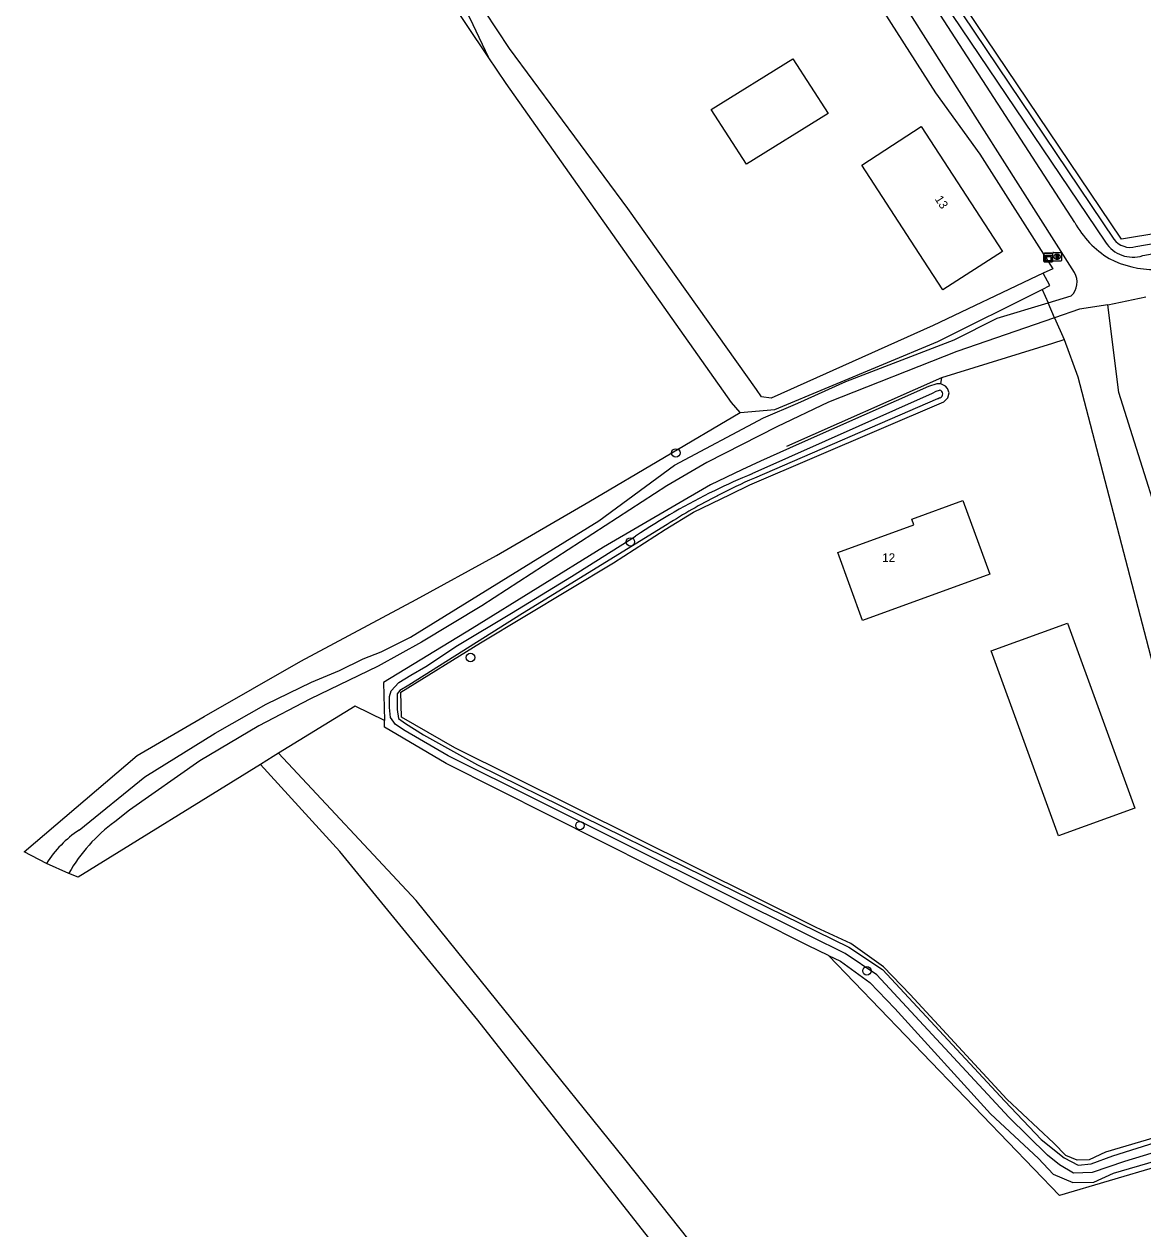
# Model space of a CAD drawing. Extents: x 163863 to 164644, y 379566 to 382155.
# Drawn here: x 164255.7 to 164384.5, y 381487.2 to 381625.9 of the extents above; entities that cross this region are included whole.
import ezdxf

# ---------------------------------------------------------------- set-up
doc = ezdxf.new("R2010")
doc.units = 0
for name, color, linetype in [('IMGEO_Boom', 7, 'Continuous'), ('IMGEO_Bouwland', 7, 'Continuous'), ('IMGEO_Erf', 7, 'Continuous'), ('IMGEO_Grasland_overig', 7, 'Continuous'), ('IMGEO_Groenvoorziening', 7, 'Continuous'), ('IMGEO_Haag', 7, 'Continuous'), ('IMGEO_Hek', 7, 'Continuous'), ('IMGEO_Kast', 7, 'Continuous'), ('IMGEO_Pand', 7, 'Continuous'), ('IMGEO_Pand_nummerreeks', 7, 'Continuous'), ('IMGEO_Rijbaan_lokaal_onverhard', 7, 'Continuous'), ('IMGEO_Rioolput', 7, 'Continuous'), ('IMGEO_Waterloop', 7, 'Continuous')]:
    doc.layers.add(name, color=color, linetype=linetype)

msp = doc.modelspace()

# ---------------------------------------------------------------- linework, layer by layer
at = {"layer": 'IMGEO_Boom'}
for centre in [(164330.75, 381576.5), (164325.53, 381566.25), (164307.12, 381552.94), (164319.72, 381533.59), (164352.76, 381516.86)]:
    msp.add_circle(centre, 0.489, dxfattribs=at)
at = {"layer": 'IMGEO_Bouwland'}
msp.add_lwpolyline([(164348.35, 381518.62), (164345.94, 381519.8), (164304.33, 381540.74), (164297.21, 381544.93), (164297.2, 381545.69)], dxfattribs=at)
at = {"layer": 'IMGEO_Erf'}
msp.add_lwpolyline([(164399.71, 381501.75), (164380.24, 381495.98), (164378.34, 381495.1), (164376.95, 381495.07), (164375.66, 381495.6), (164374.28, 381497.03), (164368.85, 381502.09), (164357.74, 381514.15), (164354.66, 381517.34), (164350.89, 381520.01), (164346.92, 381521.84), (164305.32, 381542.54), (164299.19, 381546.09), (164299.1, 381548.97), (164308.27, 381554.65), (164323.57, 381563.86), (164329.55, 381567.7), (164332.8, 381569.66), (164337.03, 381571.73), (164339.27, 381572.83), (164361.61, 381582.39), (164362.09, 381582.86), (164362.24, 381583.41), (164362.04, 381583.93), (164361.82, 381584.19), (164361.25, 381584.45)], dxfattribs=at)
at = {"layer": 'IMGEO_Grasland_overig'}
for points in [[(164309.17, 381622.09), (164287.09, 381655.07)], [(164372.93, 381595.33), (164373.62, 381593.79)], [(164262.05, 381533.06), (164269.61, 381539.21), (164277.71, 381544.24), (164283.59, 381547.57), (164288.81, 381550.12), (164292.05, 381551.44), (164294.75, 381552.79), (164296.85, 381553.59), (164300.23, 381555.29), (164321.9, 381568.69), (164330.62, 381575.1), (164340.85, 381580.53), (164344.81, 381582.22), (164350.33, 381584.74), (164362.79, 381589.53), (164367.77, 381592.02), (164373.62, 381593.79)], [(164392.11, 381552.47), (164390.65, 381553.68), (164390.08, 381554.71), (164388.77, 381561.19), (164381.76, 381583.47), (164380.51, 381593.56)], [(164374.37, 381592.06), (164363.11, 381588.17), (164348.34, 381582.35), (164342.38, 381579.5), (164334.32, 381575.4), (164329.74, 381572.7), (164308.43, 381558.91), (164301.49, 381554.72), (164296.49, 381551.95), (164288.63, 381548.14), (164282.77, 381545.07), (164275.97, 381541.06), (164267.86, 381535.37), (164266.17, 381534.03)], [(164374.37, 381592.06), (164375.48, 381589.55)], [(164361.25, 381584.45), (164361.39, 381585.17), (164374.16, 381589.15), (164375.48, 381589.55)], [(164375.48, 381589.55), (164377.05, 381585.25), (164394.23, 381519.23)], [(164361.25, 381584.45), (164360.81, 381584.45), (164359.85, 381584.14), (164344.96, 381577.54), (164340.51, 381575.55), (164338.35, 381574.54), (164334.75, 381572.82), (164322.44, 381565.66), (164307.31, 381556.3), (164297.1, 381550.07), (164297.2, 381545.69)], [(164258.3, 381529.24), (164255.73, 381530.58), (164268.74, 381541.65), (164276.47, 381546.15), (164287.59, 381552.54), (164300.85, 381559.61), (164310.1, 381564.69), (164320.74, 381570.88), (164338.17, 381581.17)], [(164297.2, 381545.69), (164293.83, 381547.35), (164285.02, 381541.92)], [(164285.02, 381541.92), (164284.42, 381541.54), (164282.94, 381540.64)], [(164409.07, 381444.14), (164409.6, 381438.92), (164393.19, 381411.03), (164380.14, 381426.39), (164361.95, 381448.81), (164345.91, 381468.69), (164324.9, 381495.18), (164300.88, 381524.96), (164285.02, 381541.92)], [(164282.94, 381540.64), (164261.94, 381527.66), (164260.87, 381528.09)], [(164392.18, 381406.36), (164355.54, 381450.6), (164307.96, 381511.18), (164292.08, 381530.61), (164282.94, 381540.64)], [(164260.87, 381528.09), (164258.3, 381529.24)], [(164348.35, 381518.62), (164349.7, 381517.97), (164353.09, 381515.54), (164355.98, 381512.51), (164367, 381500.41), (164372.5, 381495.24), (164374.19, 381493.46), (164376.45, 381492.51), (164378.9, 381492.55), (164381.15, 381493.56), (164399.72, 381498.97), (164402.22, 381489.44), (164402.44, 381487.77), (164403.46, 381487.71)], [(164404.26, 381474.32), (164397.81, 381497.74), (164374.92, 381491), (164348.35, 381518.62)]]:
    msp.add_lwpolyline(points, dxfattribs=at)
for centre, radius, start, end in [((164277.4, 381518.7), 19.01, 126.2236, 150.3885), ((164269.14, 381522.37), 12.83, 123.5518, 147.6149)]:
    msp.add_arc(centre, radius, start, end, dxfattribs=at)
at = {"layer": 'IMGEO_Groenvoorziening'}
msp.add_lwpolyline([(164342.85, 381642.58), (164344.82, 381642.8), (164360.65, 381617.95), (164365.76, 381610.9), (164374.16, 381597.69), (164373.03, 381597.19)], dxfattribs=at)
at = {"layer": 'IMGEO_Haag'}
msp.add_lwpolyline([(164407.8, 381604.43), (164407.63, 381605.35), (164382.05, 381601.1), (164338.92, 381665.18), (164338.35, 381664.78)], dxfattribs=at)
at = {"layer": 'IMGEO_Hek'}
for points in [[(164374.16, 381589.15), (164375.48, 381589.55)], [(164343.52, 381577.27), (164361.39, 381585.17)]]:
    msp.add_lwpolyline(points, dxfattribs=at)
at = {"layer": 'IMGEO_Kast'}
for p, q in [((164373.12, 381598.57), (164373.12, 381599.41)), ((164373.12, 381599.41), (164373.12, 381598.57)), ((164373.2, 381599.49), (164374.04, 381599.49)), ((164374.04, 381599.49), (164373.2, 381599.49)), ((164374.12, 381599.42), (164374.12, 381598.58)), ((164374.12, 381598.58), (164374.12, 381599.42)), ((164374.05, 381598.49), (164373.21, 381598.49)), ((164373.21, 381598.49), (164374.05, 381598.49))]:
    msp.add_line(p, q, dxfattribs=at)
for points in [[(164373.32, 381599.28), (164373.92, 381599.28), (164373.92, 381599.2), (164373.32, 381599.2), (164373.32, 381599.28)], [(164373.32, 381599.11), (164373.92, 381599.11), (164373.92, 381598.62), (164373.32, 381598.62), (164373.32, 381599.11)]]:
    msp.add_lwpolyline(points, dxfattribs=at)
msp.add_circle((164373.4, 381598.96), 0.0377, dxfattribs=at)
for centre, start, end in [((164373.2, 381599.41), 92.4484, 184.2845), ((164373.2, 381599.41), 92.4484, 184.2845), ((164374.04, 381599.41), 2.4484, 94.2845), ((164374.04, 381599.41), 2.4484, 94.2845), ((164373.2, 381598.57), 182.4484, 274.2845), ((164373.2, 381598.57), 182.4484, 274.2845), ((164374.04, 381598.57), 272.4484, 4.2845), ((164374.04, 381598.57), 272.4484, 4.2845)]:
    msp.add_arc(centre, 0.0779, start, end, dxfattribs=at)
at = {"layer": 'IMGEO_Pand'}
for points in [[(164338.91, 381609.75), (164334.83, 381616.04), (164344.23, 381621.88), (164348.31, 381615.59), (164338.91, 381609.75)], [(164358.78, 381599.46), (164352.17, 381609.65), (164354.82, 381611.38), (164359.01, 381614.1), (164368.35, 381599.71), (164361.5, 381595.27), (164358.78, 381599.46)], [(164352.26, 381557.21), (164349.42, 381565.03), (164358.15, 381568.22), (164357.92, 381568.87), (164363.81, 381571.02), (164366.9, 381562.54), (164352.26, 381557.21)], [(164367.06, 381553.7), (164375.84, 381556.9), (164383.59, 381535.61), (164374.81, 381532.42), (164367.06, 381553.7)]]:
    msp.add_lwpolyline(points, dxfattribs=at)
at = {"layer": 'IMGEO_Rijbaan_lokaal_onverhard'}
for points in [[(164376.68, 381603.04), (164360.3, 381628.34), (164336.67, 381663.83), (164319.55, 381685.45)], [(164376.65, 381597.28), (164357.73, 381627.06), (164346.74, 381643.35), (164343.74, 381644.16), (164341.85, 381643.92)], [(164373.62, 381593.79), (164376.28, 381594.59)], [(164374.37, 381592.06), (164373.62, 381593.79)], [(164380.51, 381593.56), (164377.23, 381593.05), (164374.37, 381592.06)], [(164380.51, 381593.56), (164384.86, 381594.48)]]:
    msp.add_lwpolyline(points, dxfattribs=at)
for centre, radius, start, end in [((164386.24, 381608.19), 10.85, 208.3188, 239.0619), ((164385.9, 381609.07), 11.46, 242.7973, 270.3915), ((164374.79, 381596.17), 2.17, 313.3238, 30.8642)]:
    msp.add_arc(centre, radius, start, end, dxfattribs=at)
at = {"layer": 'IMGEO_Rioolput'}
for p, q in [((164374.16, 381598.66), (164374.16, 381599.51)), ((164374.23, 381599.59), (164375.08, 381599.59)), ((164374.64, 381599.37), (164374.67, 381599.37)), ((164375.16, 381599.51), (164375.16, 381598.66)), ((164375.08, 381598.59), (164374.23, 381598.59)), ((164374.67, 381598.81), (164374.64, 381598.81))]:
    msp.add_line(p, q, dxfattribs=at)
for points in [[(164374.16, 381598.66), (164374.16, 381599.51)], [(164374.23, 381599.59), (164375.08, 381599.59)], [(164374.74, 381599.28), (164374.49, 381599.29), (164374.49, 381598.89)], [(164374.67, 381599.21), (164374.62, 381599.21), (164374.62, 381599.12)], [(164374.62, 381599.12), (164374.67, 381599.12)], [(164375.16, 381599.51), (164375.16, 381598.66)], [(164375.08, 381598.59), (164374.23, 381598.59)], [(164374.49, 381598.89), (164374.62, 381598.89), (164374.62, 381599.05), (164374.63, 381599.05)], [(164374.67, 381599.02), (164374.75, 381598.89), (164374.88, 381598.89), (164374.82, 381599.01)]]:
    msp.add_lwpolyline(points, dxfattribs=at)
for centre, radius, start, end in [((164374.23, 381599.51), 0.0765, 91.552, 178.448), ((164374.23, 381599.51), 0.0765, 91.552, 178.448), ((164374.68, 381599.11), 0.0964, 77.0061, 93.1865), ((164374.65, 381599.31), 0.19, 274.7715, 282.9687), ((164374.69, 381599.17), 0.0378, 276.6634, 79.6772), ((164374.74, 381599.18), 0.109, 350.3612, 89.416), ((164374.74, 381599.17), 0.112, 277.5842, 350.9817), ((164375.08, 381599.51), 0.0765, 1.552, 88.448), ((164375.08, 381599.51), 0.0765, 1.552, 88.448), ((164374.23, 381598.66), 0.0765, 181.552, 268.448), ((164374.23, 381598.66), 0.0765, 181.552, 268.448), ((164374.63, 381599), 0.0533, 26.0293, 88.6989), ((164374.73, 381598.96), 0.108, 29.5134, 73.7905), ((164375.08, 381598.66), 0.0765, 271.552, 358.448), ((164375.08, 381598.66), 0.0765, 271.552, 358.448)]:
    msp.add_arc(centre, radius, start, end, dxfattribs=at)
for centre, major_axis, ratio, start_param, end_param in [((164374.64, 381599.09), (-0.387, 0.002), 0.722429, 4.712389, 7.853982), ((164374.67, 381599.09), (-0.39, 0.002), 0.717154, 1.570796, 4.712389)]:
    msp.add_ellipse(centre, major_axis=major_axis, ratio=ratio, start_param=start_param, end_param=end_param, dxfattribs=at)
at = {"layer": 'IMGEO_Waterloop'}
for points in [[(164336.62, 381665.42), (164380.22, 381600.77)], [(164338.35, 381664.78), (164381.18, 381601.12)], [(164288.22, 381655.95), (164304.6, 381633.51), (164306.3, 381628.05), (164307.37, 381625.84), (164309.17, 381622.09)], [(164373.03, 381597.19), (164372.33, 381596.86), (164360.39, 381591.19), (164341.72, 381582.81), (164340.63, 381582.95), (164340.03, 381583.8), (164325.22, 381604.63), (164311.6, 381623.07), (164308.78, 381627.38), (164308.85, 381629.06)], [(164338.17, 381581.17), (164337.15, 381582.3), (164311.21, 381619.04), (164309.17, 381622.09)], [(164384.53, 381599.22), (164409.57, 381603.76), (164409.37, 381604.7)], [(164383.73, 381600.26), (164407.8, 381604.43)], [(164372.93, 381595.33), (164373.82, 381595.78), (164373.03, 381597.19)], [(164338.17, 381581.17), (164342.17, 381581.51), (164360.91, 381589.33), (164372.93, 381595.33)], [(164339.54, 381574.12), (164360.32, 381583.37), (164360.72, 381583.6), (164361.11, 381583.72)], [(164361.17, 381582.83), (164360.96, 381582.74), (164360.87, 381582.71), (164339.8, 381573.6)], [(164329.77, 381568.26), (164313.12, 381558.01), (164300.03, 381549.74), (164299, 381549.16), (164298.67, 381548.78), (164298.67, 381546.95), (164298.84, 381545.93), (164299.65, 381545.33), (164301.71, 381544.03), (164307.92, 381540.57), (164331.96, 381528.77), (164350.67, 381519.59), (164354.57, 381517.03), (164368.63, 381501.86), (164372.82, 381497.44), (164375.45, 381495.32), (164377.06, 381494.48), (164378.58, 381494.65), (164381.07, 381495.55), (164392.99, 381499.33)], [(164395.31, 381498.82), (164382.41, 381494.93), (164378.7, 381493.64), (164376.54, 381493.58), (164374.92, 381494.53), (164373.54, 381495.65), (164369.1, 381500), (164353.9, 381516.4), (164350.27, 381518.88), (164346.22, 381520.84), (164304.55, 381541.63), (164299.58, 381544.5), (164298.49, 381545.22), (164297.92, 381546.04), (164297.78, 381547.18), (164297.8, 381548.46), (164298, 381549.11), (164298.88, 381550.05), (164300.24, 381550.9), (164301.98, 381551.89), (164305.64, 381554.34), (164311.83, 381558.05), (164318.74, 381562.27), (164326.13, 381566.92)]]:
    msp.add_lwpolyline(points, dxfattribs=at)
for centre, radius, start, end in [((164383.39, 381602.82), 3.78, 212.9561, 287.5967), ((164383.08, 381602.55), 2.38, 216.8405, 285.7795), ((164361.02, 381583.27), 0.461, 289.4939, 79.0169), ((164369.92, 381501.27), 78.92, 112.6358, 116.099), ((164370.05, 381504.51), 75.42, 113.6483, 117.2335), ((164369.5, 381502.22), 77.89, 116.129, 123.8321), ((164369.14, 381506.27), 73.44, 117.2293, 122.4145)]:
    msp.add_arc(centre, radius, start, end, dxfattribs=at)

# ---------------------------------------------------------------- texts
at = {"layer": 'IMGEO_Pand_nummerreeks'}
msp.add_text('13', height=1, rotation=302.9942, dxfattribs=at).set_placement((164360.53, 381605.74))
msp.add_text('12', height=1, dxfattribs=at).set_placement((164354.52, 381563.94))

doc.saveas('drawing.dxf')
